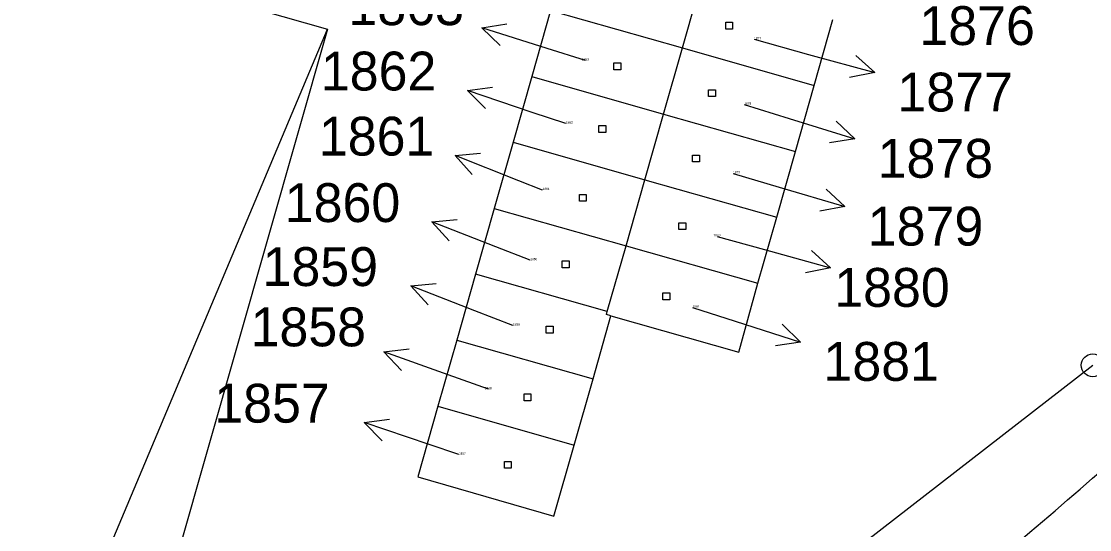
# Model space of a CAD drawing. Extents: x -795483 to -789093, y -1112258 to -1108741.
# Drawn here: x -792032.53 to -791985.76, y -1109657.97 to -1109635.73 of the extents above; entities that cross this region are included whole.
import ezdxf

# ---------------------------------------------------------------- set-up
doc = ezdxf.new("R2010")
doc.units = 0
for name, color, linetype in [('Komunikace', 7, 'Continuous'), ('Vrstva 1', 7, 'Continuous'), ('Vrstva 10', 7, 'Continuous'), ('Vrstva 15', 7, 'Continuous'), ('Vrstva 16', 7, 'Continuous'), ('Vrstva 25', 7, 'Continuous'), ('Vrstva 28', 7, 'Continuous')]:
    doc.layers.add(name, color=color, linetype=linetype)

msp = doc.modelspace()

# ---------------------------------------------------------------- linework, layer by layer
at = {"layer": 'Komunikace'}
for p, q in [((-792000.45, -1109636.51), (-791998.06, -1109637.17)), ((-792007.83, -1109637.44), (-792009.51, -1109636.91)), ((-792000.88, -1109639.37), (-791998.91, -1109639.98)), ((-792008.69, -1109640.2), (-792010.16, -1109639.71)), ((-792009.71, -1109643.11), (-792010.75, -1109642.7)), ((-792001.37, -1109642.38), (-791999.35, -1109642.98)), ((-792002.07, -1109645.14), (-791999.99, -1109645.71)), ((-792010.25, -1109646.18), (-792011.76, -1109645.59)), ((-792011.01, -1109649.04), (-792012.68, -1109648.39)), ((-792003.14, -1109648.25), (-792001.27, -1109648.85)), ((-792012.08, -1109651.83), (-792013.84, -1109651.2)), ((-792013.38, -1109654.69), (-792014.68, -1109654.25))]:
    msp.add_line(p, q, dxfattribs=at)
at = {"layer": 'Vrstva 1'}
for p, q in [((-792086.45, -1109616.83), (-792019.13, -1109636.07)), ((-792003.59, -1109636.89), (-792002.77, -1109634.01)), ((-792009.36, -1109635.25), (-792010.18, -1109638.14)), ((-792009.36, -1109635.25), (-792003.59, -1109636.89)), ((-791997.82, -1109638.53), (-791997, -1109635.65)), ((-792032.19, -1109667.09), (-792019.13, -1109636.07)), ((-792004.41, -1109639.78), (-792003.59, -1109636.89)), ((-792003.59, -1109636.89), (-791997.82, -1109638.53)), ((-792010.18, -1109638.14), (-792011, -1109641.02)), ((-792010.18, -1109638.14), (-792004.41, -1109639.78)), ((-791998.64, -1109641.42), (-791997.82, -1109638.53)), ((-792005.23, -1109642.66), (-792004.41, -1109639.78)), ((-792004.41, -1109639.78), (-791998.64, -1109641.42)), ((-792011, -1109641.02), (-792011.83, -1109643.91)), ((-792011, -1109641.02), (-792005.23, -1109642.66)), ((-791999.46, -1109644.3), (-791998.64, -1109641.42)), ((-792006.05, -1109645.55), (-792005.23, -1109642.66)), ((-792005.23, -1109642.66), (-791999.46, -1109644.3)), ((-792011.83, -1109643.91), (-792012.65, -1109646.79)), ((-792011.83, -1109643.91), (-792006.05, -1109645.55)), ((-792000.28, -1109647.19), (-791999.46, -1109644.3)), ((-792006.88, -1109648.43), (-792006.05, -1109645.55)), ((-792006.05, -1109645.55), (-792000.28, -1109647.19)), ((-792012.65, -1109646.79), (-792013.47, -1109649.68)), ((-792006.88, -1109648.43), (-792012.65, -1109646.79)), ((-792001.11, -1109650.21), (-792000.28, -1109647.19)), ((-792007.5, -1109651.37), (-792006.72, -1109648.61)), ((-792006.91, -1109648.56), (-792006.88, -1109648.43)), ((-792006.72, -1109648.61), (-792006.91, -1109648.56)), ((-792006.72, -1109648.61), (-792001.11, -1109650.21)), ((-792013.47, -1109649.68), (-792014.29, -1109652.57)), ((-792013.47, -1109649.68), (-792007.5, -1109651.37)), ((-792022.82, -1109679.59), (-791985.62, -1109650.78)), ((-792008.33, -1109654.27), (-792007.5, -1109651.37)), ((-792014.29, -1109652.57), (-792015.17, -1109655.67)), ((-792014.29, -1109652.57), (-792008.33, -1109654.27)), ((-792009.21, -1109657.39), (-792008.33, -1109654.27)), ((-792015.17, -1109655.67), (-792009.21, -1109657.39))]:
    msp.add_line(p, q, dxfattribs=at)
msp.add_lwpolyline([(-792019.13, -1109636.07), (-792028.31, -1109668.24), (-792032.19, -1109667.09)], dxfattribs=at)
at = {"layer": 'Vrstva 10'}
msp.add_arc((-792153.505, -1109463.628), 255.116, 307.56815, 317.98901, dxfattribs=at)
at = {"layer": 'Vrstva 16'}
for p, q in [((-792012.372, -1109636.012), (-792011.268, -1109635.834)), ((-792009.51, -1109636.91), (-792012.372, -1109636.012)), ((-792012.372, -1109636.012), (-792011.567, -1109636.788)), ((-791998.06, -1109637.17), (-791995.168, -1109637.969)), ((-791995.168, -1109637.969), (-791995.999, -1109637.221)), ((-791995.168, -1109637.969), (-791996.265, -1109638.184)), ((-792013.003, -1109638.753), (-792011.896, -1109638.598)), ((-792010.16, -1109639.71), (-792013.003, -1109638.753)), ((-792013.003, -1109638.753), (-792012.215, -1109639.546)), ((-791998.91, -1109639.98), (-791996.044, -1109640.868)), ((-791996.044, -1109640.868), (-791996.851, -1109640.094)), ((-791996.044, -1109640.868), (-791997.147, -1109641.049)), ((-792013.54, -1109641.599), (-792012.427, -1109641.501)), ((-792010.75, -1109642.7), (-792013.54, -1109641.599)), ((-792013.54, -1109641.599), (-792012.794, -1109642.431)), ((-791999.35, -1109642.98), (-791996.474, -1109643.836)), ((-791996.474, -1109643.836), (-791997.29, -1109643.071)), ((-791996.474, -1109643.836), (-791997.576, -1109644.03)), ((-792014.557, -1109644.506), (-792013.444, -1109644.401)), ((-792011.76, -1109645.59), (-792014.557, -1109644.506)), ((-792014.557, -1109644.506), (-792013.805, -1109645.333)), ((-791999.99, -1109645.71), (-791997.099, -1109646.512)), ((-791997.099, -1109646.512), (-791997.929, -1109645.762)), ((-791997.099, -1109646.512), (-791998.196, -1109646.726)), ((-792015.477, -1109647.307), (-792014.364, -1109647.201)), ((-792012.68, -1109648.39), (-792015.477, -1109647.307)), ((-792015.477, -1109647.307), (-792014.725, -1109648.134)), ((-792001.27, -1109648.85), (-791998.412, -1109649.762)), ((-791998.412, -1109649.762), (-791999.212, -1109648.981)), ((-791998.412, -1109649.762), (-791999.516, -1109649.934)), ((-792016.667, -1109650.196), (-792015.557, -1109650.059)), ((-792013.84, -1109651.2), (-792016.667, -1109650.196)), ((-792016.667, -1109650.196), (-792015.892, -1109651.002)), ((-792017.521, -1109653.288), (-792016.414, -1109653.135)), ((-792014.68, -1109654.25), (-792017.521, -1109653.288)), ((-792017.521, -1109653.288), (-792016.734, -1109654.082))]:
    msp.add_line(p, q, dxfattribs=at)
at = {"layer": 'Vrstva 25'}
for p, q in [((-792001.69, -1109635.76), (-792001.39, -1109635.76)), ((-792001.69, -1109636.06), (-792001.69, -1109635.76)), ((-792001.39, -1109635.76), (-792001.39, -1109636.06)), ((-792001.39, -1109636.06), (-792001.69, -1109636.06)), ((-792006.59, -1109637.54), (-792006.29, -1109637.54)), ((-792006.59, -1109637.84), (-792006.59, -1109637.54)), ((-792006.29, -1109637.54), (-792006.29, -1109637.84)), ((-792006.29, -1109637.84), (-792006.59, -1109637.84)), ((-792002.44, -1109638.72), (-792002.14, -1109638.72)), ((-792002.44, -1109639.02), (-792002.44, -1109638.72)), ((-792002.14, -1109639.02), (-792002.44, -1109639.02)), ((-792002.14, -1109638.72), (-792002.14, -1109639.02)), ((-792007.24, -1109640.29), (-792006.94, -1109640.29)), ((-792007.24, -1109640.59), (-792007.24, -1109640.29)), ((-792006.94, -1109640.29), (-792006.94, -1109640.59)), ((-792006.94, -1109640.59), (-792007.24, -1109640.59)), ((-792003.14, -1109641.58), (-792002.84, -1109641.58)), ((-792003.14, -1109641.88), (-792003.14, -1109641.58)), ((-792002.84, -1109641.58), (-792002.84, -1109641.88)), ((-792002.84, -1109641.88), (-792003.14, -1109641.88)), ((-792008.1, -1109643.3), (-792007.8, -1109643.3)), ((-792008.1, -1109643.6), (-792008.1, -1109643.3)), ((-792007.8, -1109643.6), (-792008.1, -1109643.6)), ((-792007.8, -1109643.3), (-792007.8, -1109643.6)), ((-792003.74, -1109644.54), (-792003.44, -1109644.54)), ((-792003.74, -1109644.84), (-792003.74, -1109644.54)), ((-792003.44, -1109644.54), (-792003.44, -1109644.84)), ((-792003.44, -1109644.84), (-792003.74, -1109644.84)), ((-792008.85, -1109646.21), (-792008.55, -1109646.21)), ((-792008.85, -1109646.51), (-792008.85, -1109646.21)), ((-792008.55, -1109646.51), (-792008.85, -1109646.51)), ((-792008.55, -1109646.21), (-792008.55, -1109646.51)), ((-792004.44, -1109647.61), (-792004.14, -1109647.61)), ((-792004.44, -1109647.91), (-792004.44, -1109647.61)), ((-792004.14, -1109647.91), (-792004.44, -1109647.91)), ((-792004.14, -1109647.61), (-792004.14, -1109647.91)), ((-792009.55, -1109649.07), (-792009.25, -1109649.07)), ((-792009.55, -1109649.37), (-792009.55, -1109649.07)), ((-792009.25, -1109649.07), (-792009.25, -1109649.37)), ((-792009.25, -1109649.37), (-792009.55, -1109649.37)), ((-792010.52, -1109652.03), (-792010.22, -1109652.03)), ((-792010.52, -1109652.33), (-792010.52, -1109652.03)), ((-792010.22, -1109652.03), (-792010.22, -1109652.33)), ((-792010.22, -1109652.33), (-792010.52, -1109652.33)), ((-792011.38, -1109654.99), (-792011.08, -1109654.99)), ((-792011.38, -1109655.29), (-792011.38, -1109654.99)), ((-792011.08, -1109655.29), (-792011.38, -1109655.29)), ((-792011.08, -1109654.99), (-792011.08, -1109655.29))]:
    msp.add_line(p, q, dxfattribs=at)
at = {"layer": 'Vrstva 28'}
msp.add_circle((-791985.62, -1109650.78), 0.5, dxfattribs=at)

# ---------------------------------------------------------------- texts
at = {"layer": 'Vrstva 15'}
for s, p in [('1877', (-792000.45, -1109636.51)), ('1863', (-792007.99, -1109637.44)), ('1878', (-792000.88, -1109639.37)), ('1862', (-792008.69, -1109640.2)), ('1879', (-792001.37, -1109642.38)), ('1861', (-792009.71, -1109643.11)), ('1880', (-792002.228, -1109645.14)), ('1860', (-792010.25, -1109646.18)), ('1881', (-792003.14, -1109648.25)), ('1859', (-792011.01, -1109649.04)), ('1858', (-792012.24, -1109651.83)), ('1857', (-792013.38, -1109654.69))]:
    msp.add_text(s, height=0.1, dxfattribs=at).set_placement(p)
at = {"layer": 'Vrstva 16'}
for s, p in [('1863', (-792018.21, -1109635.89)), ('1876', (-791993.21, -1109636.76)), ('1862', (-792019.419, -1109638.75)), ('1877', (-791994.17, -1109639.67)), ('1861', (-792019.506, -1109641.6)), ('1878', (-791995.04, -1109642.57)), ('1860', (-792020.998, -1109644.51)), ('1879', (-791995.47, -1109645.54)), ('1859', (-792021.972, -1109647.31)), ('1880', (-791996.939, -1109648.22)), ('1858', (-792022.496, -1109649.95)), ('1881', (-791997.41, -1109651.46)), ('1857', (-792024.085, -1109653.29))]:
    msp.add_text(s, height=1.7, dxfattribs=at).set_placement(p)

doc.saveas('drawing.dxf')
